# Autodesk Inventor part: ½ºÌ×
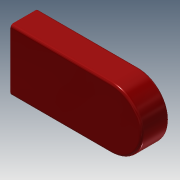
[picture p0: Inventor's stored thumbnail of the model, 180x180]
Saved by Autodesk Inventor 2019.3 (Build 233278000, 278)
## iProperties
Created: 2012-09
Part Number: ½ºÌ×
Material: Ogólny
Document SubType Name: Modeling
Designer: CADENGINEERING4
Density: 1 g/cm^3
Appearance: Czerwona
Author: CADENGINEERING4
Revision Number: ÈÎºÎ
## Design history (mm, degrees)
feature "³é¿Ç1"
node "Bryła1"
